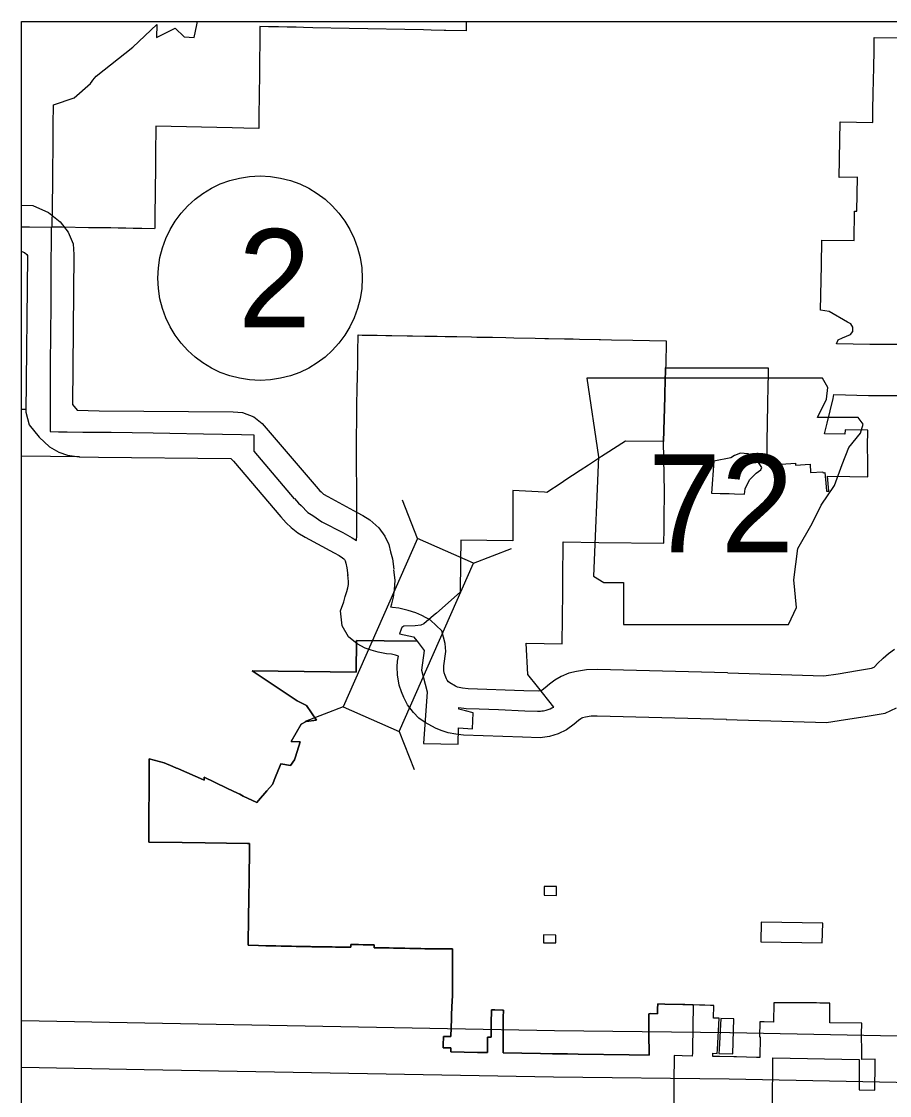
# Model space of a CAD drawing. Extents: x 670147 to 673275, y 705573 to 707613.
# Drawn here: x 670257.2 to 670341.3, y 707417.7 to 707521.7 of the extents above; entities that cross this region are included whole.
import ezdxf

# ---------------------------------------------------------------- set-up
doc = ezdxf.new("R2010")
doc.units = 0
for name, color, linetype in [('10', 7, 'Continuous'), ('20', 7, 'Continuous'), ('21', 7, 'Continuous'), ('27', 7, 'Continuous'), ('6', 7, 'Continuous'), ('R_NoPlot', 7, 'Continuous')]:
    doc.layers.add(name, color=color, linetype=linetype)

msp = doc.modelspace()

# ---------------------------------------------------------------- linework, layer by layer
at = {"layer": '10'}
msp.add_line((670260.81, 707480.01), (670261.67, 707479.72), dxfattribs=at)
for points in [[(670257.19, 707503.95), (670258.28, 707503.9), (670259.81, 707503.23), (670260.94, 707502.34), (670261.72, 707501.32), (670262.19, 707500.18), (670262.27, 707499.17), (670262.13, 707484.64), (670262.58, 707484.08)], [(670257.19, 707499.44), (670257.24, 707499.44), (670257.48, 707499.34), (670257.71, 707499.16), (670257.77, 707499.08), (670257.77, 707499), (670257.62, 707483.9), (670257.94, 707482.66), (670258.91, 707481.46), (670259.9, 707480.55), (670260.81, 707480.01)], [(670257.68, 707484.14), (670257.19, 707484.14)], [(670262.58, 707484.08), (670264.72, 707484.03), (670277.72, 707483.91), (670278.61, 707483.86), (670279.72, 707483.45), (670280.5, 707482.8), (670281.11, 707482.12), (670285.73, 707476.69), (670286.09, 707476.28), (670286.22, 707476.16), (670286.47, 707475.96), (670286.87, 707475.73), (670289.72, 707474.19), (670290.26, 707473.87), (670290.96, 707473.46), (670291.83, 707472.7), (670292.39, 707471.87), (670292.78, 707471.07), (670292.96, 707470.37), (670293.13, 707469.69), (670293.28, 707468.69)], [(670262.82, 707479.58), (670257.19, 707479.64)], [(670261.67, 707479.72), (670262.79, 707479.57), (670264.65, 707479.53), (670277.49, 707479.41), (670277.73, 707479.16), (670282.31, 707473.76), (670282.83, 707473.16), (670283.31, 707472.72), (670283.96, 707472.22), (670284.67, 707471.8), (670287.5, 707470.28), (670287.96, 707470), (670288.31, 707469.79), (670288.43, 707469.69), (670288.48, 707469.61), (670288.54, 707469.49), (670288.61, 707469.26), (670288.71, 707468.83), (670288.82, 707468.06)], [(670325.61, 707458.63), (670312.99, 707458.96), (670311.94, 707458.94), (670310.97, 707458.76), (670310.22, 707458.6), (670309.48, 707458.3), (670308.87, 707457.94), (670308.35, 707457.54), (670307.93, 707457.19), (670307.65, 707456.97), (670307.57, 707456.93), (670307.43, 707456.89), (670307.25, 707456.87), (670305.86, 707456.9), (670300.46, 707457.09), (670299.93, 707457.17), (670299.61, 707457.22), (670299.44, 707457.27), (670299.26, 707457.35), (670298.69, 707457.67), (670298.56, 707457.76), (670298.55, 707457.78), (670298.43, 707457.93), (670298.36, 707458.06), (670298.24, 707458.4), (670298.14, 707458.65), (670298.11, 707458.86), (670298.11, 707459.07), (670298.12, 707459.33), (670298.31, 707460.7), (670298.24, 707461.5), (670297.92, 707462.7), (670296.83, 707463.75), (670295.97, 707464.2), (670295.39, 707464.46), (670294.67, 707464.69), (670293.75, 707464.92), (670293.13, 707464.97), (670292.97, 707465), (670293.07, 707465.33), (670293.23, 707465.99), (670293.35, 707466.7), (670293.39, 707467.63), (670293.28, 707468.62)], [(670325.49, 707454.13), (670312.98, 707454.46), (670312.39, 707454.45), (670311.83, 707454.34), (670311.56, 707454.29), (670311.49, 707454.26), (670311.39, 707454.2), (670311.16, 707454.02), (670310.75, 707453.68), (670310.01, 707453.11), (670309.2, 707452.73), (670308.36, 707452.47), (670307.45, 707452.36), (670305.73, 707452.41), (670300.03, 707452.6), (670299.27, 707452.72), (670298.54, 707452.82), (670297.86, 707453.06), (670297.3, 707453.28), (670296.31, 707453.85), (670295.69, 707454.27), (670295.16, 707454.79), (670294.59, 707455.54), (670294.23, 707456.27), (670294.02, 707456.81), (670293.78, 707457.46), (670293.61, 707458.45), (670293.6, 707459.22), (670293.64, 707459.78), (670293.71, 707460.27), (670293.42, 707460.37), (670293.03, 707460.46), (670292.56, 707460.5), (670291.74, 707460.65), (670291.08, 707460.84), (670290.49, 707461.04), (670289.73, 707461.44), (670288.88, 707462.14), (670288.25, 707463.19), (670288.1, 707464.65), (670288.41, 707465.53), (670288.57, 707466.03), (670288.73, 707466.52), (670288.81, 707466.88), (670288.87, 707467.19), (670288.88, 707467.49), (670288.81, 707468.13)], [(670325.62, 707458.63), (670334.94, 707458.35), (670336.33, 707458.55), (670338.18, 707458.86), (670339.55, 707459.09), (670339.8, 707459.2), (670339.87, 707459.26), (670340.14, 707459.54), (670340.68, 707460.08), (670341.21, 707460.53), (670341.76, 707460.93)], [(670325.48, 707454.13), (670335.19, 707453.84), (670337.03, 707454.11), (670338.92, 707454.42), (670340.87, 707454.75), (670341.97, 707455.25)], [(670325.82, 707423.78), (670308.82, 707423.98), (670269.15, 707424.71), (670257.19, 707424.94)], [(670402.71, 707422.39), (670387.99, 707422.45), (670348.51, 707423.34), (670325.84, 707423.78)], [(670325.77, 707419.28), (670308.75, 707419.48), (670269.07, 707420.21), (670257.19, 707420.43)], [(670406.07, 707417.87), (670387.93, 707417.95), (670348.42, 707418.84), (670325.75, 707419.28)]]:
    msp.add_lwpolyline(points, dxfattribs=at)
at = {"layer": '20'}
for p, q in [((670295.55, 707471.67), (670294.11, 707475.36)), ((670300.98, 707469.27), (670304.67, 707470.7)), ((670288.36, 707455.36), (670284.67, 707453.93)), ((670293.79, 707452.96), (670295.23, 707449.27))]:
    msp.add_line(p, q, dxfattribs=at)
msp.add_lwpolyline([(670293.79, 707452.96), (670300.98, 707469.27), (670295.55, 707471.67), (670288.36, 707455.36)], close=True, dxfattribs=at)
at = {"layer": '21'}
msp.add_lwpolyline([(670311.97, 707487.18), (670313.11, 707479.57), (670312.6, 707468.02), (670313.62, 707467.39), (670315.52, 707467.39), (670315.52, 707463.33), (670331.51, 707463.33), (670332.27, 707464.98), (670332.02, 707467.64), (670332.4, 707470.69), (670333.79, 707473.1), (670334.68, 707474.87), (670335.95, 707476.78), (670336.71, 707478.81), (670337.35, 707480.46), (670338.49, 707481.85), (670338.74, 707482.74), (670338.24, 707483.38), (670334.3, 707483.38), (670335.19, 707485.15), (670335.32, 707486.29), (670334.79, 707487.17)], close=True, dxfattribs=at)
at = {"layer": '27'}
msp.add_circle((670280.31, 707496.87), 9.9, dxfattribs=at)
at = {"layer": '6'}
for points in [[(670300.29, 707521.73), (670300.27, 707520.82), (670298.3, 707520.86), (670298.16, 707520.86), (670296.89, 707520.89), (670296.14, 707520.91), (670288.95, 707521.06), (670285.42, 707521.13), (670284.51, 707521.15), (670283.8, 707521.17), (670282.94, 707521.18), (670282.09, 707521.2), (670281.14, 707521.22), (670280.3, 707521.24), (670280.29, 707520.79), (670280.29, 707520.49), (670280.28, 707519.38), (670280.26, 707518.27), (670280.26, 707517.77), (670280.25, 707517.15), (670280.24, 707516.04), (670280.23, 707515.21), (670280.23, 707514.77), (670280.22, 707514.48), (670280.2, 707512.71), (670280.2, 707512.57), (670280.19, 707511.38), (670278.74, 707511.41), (670277.62, 707511.44), (670270.21, 707511.6), (670270.19, 707508.89), (670270.18, 707507.74), (670270.17, 707507.04), (670270.17, 707506.62), (670270.16, 707506.34), (670270.15, 707505.64), (670270.14, 707504.55), (670270.12, 707503.55), (670270.11, 707502.69), (670270.1, 707501.7), (670270.09, 707501.66), (670268.87, 707501.68), (670268.01, 707501.69), (670267.29, 707501.71), (670266.57, 707501.72), (670265.86, 707501.73), (670265.13, 707501.74), (670264.41, 707501.75), (670263.69, 707501.76), (670261.14, 707501.8), (670260.18, 707501.81), (670260.18, 707502.14), (670260.2, 707503.5), (670260.21, 707504.49), (670260.22, 707505.55), (670260.23, 707506.26), (670260.23, 707506.97), (670260.24, 707507.75), (670260.25, 707509.18), (670260.26, 707509.48), (670260.28, 707511.73), (670260.3, 707513.67), (670262.3, 707514.34), (670263.87, 707515.71), (670264.05, 707515.96), (670264.12, 707516.04), (670264.42, 707516.43), (670267.98, 707519.24), (670270.31, 707521.45), (670270.29, 707520.19), (670272.09, 707521.07), (670272.96, 707520.25), (670273.93, 707520.17), (670274.18, 707521.4), (670274.24, 707521.73)], [(670344.39, 707490.45), (670339.39, 707490.45), (670336.17, 707490.52), (670336.32, 707490.9), (670336.74, 707491.08), (670337.52, 707491.4), (670337.73, 707491.7), (670337.74, 707492.13), (670337.53, 707492.45), (670337.23, 707492.62), (670335.43, 707493.64), (670334.61, 707493.78), (670334.69, 707498.13), (670334.74, 707500.54), (670337.88, 707500.51), (670337.91, 707503.37), (670338.14, 707503.36), (670338.19, 707506.64), (670336.42, 707506.62), (670336.52, 707512.02), (670339.67, 707511.96), (670339.69, 707513.14), (670339.72, 707514.78), (670339.74, 707516.01), (670339.77, 707517.32), (670339.79, 707518.9), (670339.82, 707520.19), (670342.02, 707520.16)], [(670257.19, 707501.85), (670257.97, 707501.84), (670260.07, 707501.8), (670260.06, 707499.8), (670260.05, 707499.03), (670260.03, 707493.82), (670260.02, 707491.89), (670260.01, 707491.66), (670259.99, 707488.31), (670259.97, 707484.7), (670259.96, 707482.01), (670260.77, 707482), (670261.63, 707481.99), (670263.15, 707481.97), (670265.7, 707481.94), (670265.89, 707481.94), (670269.94, 707481.89), (670271.57, 707481.86), (670274.84, 707481.8), (670278.51, 707481.73), (670279.72, 707481.71), (670279.71, 707481.05), (670279.71, 707480.1), (670283.61, 707475.51), (670283.64, 707475.53), (670284.02, 707475.09), (670284.29, 707474.85), (670284.95, 707474.18), (670285.43, 707473.87), (670286.28, 707473.28), (670288.33, 707472.24), (670289.24, 707471.72), (670289.65, 707471.47), (670289.7, 707471.94), (670289.68, 707474.66), (670289.67, 707476.31), (670289.67, 707476.69), (670289.66, 707478.51), (670289.65, 707479.69), (670289.64, 707480.79), (670289.64, 707481.07), (670289.64, 707481.53), (670289.67, 707483.07), (670289.69, 707484.55), (670289.73, 707486.2), (670289.73, 707486.57), (670289.74, 707486.93), (670289.78, 707488.93), (670289.79, 707489.71), (670289.83, 707491.37), (670290.21, 707491.36), (670291.65, 707491.34), (670292.49, 707491.32), (670293.08, 707491.31), (670294.55, 707491.29), (670295.07, 707491.28), (670296.26, 707491.26), (670296.58, 707491.25), (670296.69, 707491.25), (670297.05, 707491.25), (670297.48, 707491.24), (670298.24, 707491.23), (670299.36, 707491.21), (670300.8, 707491.18), (670301.32, 707491.17), (670301.95, 707491.16), (670302.82, 707491.14), (670304.11, 707491.12), (670304.91, 707491.1), (670306.96, 707491.06), (670307.89, 707491.04), (670308.26, 707491.04), (670309.81, 707491.01), (670310.15, 707491), (670310.63, 707490.99), (670311.25, 707490.97), (670313.16, 707490.93), (670313.3, 707490.93), (670314.37, 707490.91), (670316.42, 707490.86), (670319.67, 707490.79), (670319.61, 707488.42), (670319.6, 707488.19)], [(670319.6, 707488.19), (670319.56, 707486.71), (670319.54, 707485.93), (670319.52, 707485.37), (670319.4, 707481.05), (670315.7, 707481.09), (670313.76, 707479.83), (670313.4, 707479.59), (670312.13, 707478.76), (670311.32, 707478.23), (670309.85, 707477.27), (670309.72, 707477.18), (670309.48, 707477.03), (670308.09, 707476.12), (670307.87, 707476.13), (670304.8, 707476.31), (670304.8, 707475.44), (670304.81, 707471.42), (670299.75, 707471.51), (670299.74, 707469.41), (670299.71, 707466.46), (670297.39, 707464.44), (670297.11, 707464.19), (670296.18, 707463.38), (670295.89, 707463.27), (670295.35, 707463.19), (670294.25, 707463.15), (670294.04, 707463.04), (670293.98, 707462.87), (670293.81, 707462.42), (670293.81, 707462.42), (670295.18, 707462.12), (670295.53, 707461.71), (670292.34, 707461.75), (670289.66, 707461.79), (670289.61, 707458.72), (670279.56, 707458.85), (670283.91, 707455.95), (670284.8, 707455.48), (670285.78, 707454.06), (670284.79, 707453.92), (670284.3, 707453.68), (670283.31, 707451.98), (670284.2, 707451.97), (670283.74, 707450.52), (670283.64, 707450.21), (670283.27, 707449.68), (670282.33, 707449.83), (670282.26, 707449.67), (670281.8, 707448.57), (670281.5, 707447.84), (670280.96, 707447.23), (670280.15, 707446.27), (670280.01, 707446.1), (670278.68, 707446.71), (670278.34, 707446.88), (670278.13, 707446.98), (670277.15, 707447.45), (670275.9, 707448.06), (670274.88, 707448.55), (670274.89, 707448.26), (670274.54, 707448.42), (670272.69, 707449.22), (670272.33, 707449.38), (670272.23, 707449.42), (670271.86, 707449.58), (670271.01, 707449.93), (670269.57, 707450.33), (670269.56, 707447.38), (670269.54, 707444.92), (670269.53, 707442.25), (670272.76, 707442.21), (670275, 707442.18), (670277.07, 707442.15), (670279.09, 707442.12), (670279.3, 707442.12), (670279.29, 707441.31), (670279.28, 707440.84), (670279.28, 707440.36), (670279.27, 707439.89), (670279.26, 707439.42), (670279.25, 707438.95), (670279.25, 707438.47), (670279.24, 707438), (670279.23, 707437.53), (670279.23, 707437.2), (670279.23, 707437.06), (670279.22, 707436.7), (670279.22, 707436.58), (670279.21, 707436.11), (670279.2, 707435.64), (670279.2, 707435.16), (670279.19, 707434.69), (670279.18, 707434.22), (670279.18, 707433.77), (670279.17, 707433.55), (670279.16, 707432.95), (670279.16, 707432.26), (670280.17, 707432.23), (670280.86, 707432.21)], [(670319.47, 707474.31), (670319.48, 707475.46), (670319.49, 707476.18), (670319.4, 707481.05), (670319.52, 707485.37), (670319.54, 707485.93), (670319.56, 707486.71), (670319.6, 707488.19), (670321.84, 707488.19), (670323.38, 707488.2), (670329.52, 707488.2), (670329.49, 707485.78), (670329.48, 707485.38), (670329.47, 707484.49), (670329.45, 707482.98), (670329.42, 707480.9), (670329.41, 707479.85), (670329.41, 707479.69), (670329.4, 707478.75), (670332.18, 707478.94), (670332.19, 707478.75), (670333.6, 707478.84), (670333.65, 707478.04), (670334.84, 707478.12), (670334.85, 707478.03), (670335.03, 707478.04), (670335.15, 707476.66), (670335.19, 707476.23), (670335.41, 707476.23), (670335.28, 707477.7), (670337.45, 707477.66), (670339.2, 707477.63), (670339.18, 707479.13), (670339.16, 707480.57), (670339.19, 707482.15), (670336.99, 707482.18), (670336.95, 707481.75), (670334.99, 707481.8), (670335.24, 707482.82), (670335.83, 707485.21), (670335.91, 707485.61), (670339.27, 707485.52), (670341.99, 707485.5)], [(670279.21, 707436.11), (670279.22, 707436.58), (670279.22, 707436.7), (670279.23, 707437.06), (670279.23, 707437.2), (670279.23, 707437.53), (670279.24, 707438), (670279.25, 707438.47), (670279.25, 707438.95), (670279.26, 707439.42), (670279.27, 707439.89), (670279.28, 707440.36), (670279.28, 707440.84), (670279.29, 707441.31), (670279.3, 707442.12), (670279.09, 707442.12), (670277.07, 707442.15), (670275, 707442.18), (670272.76, 707442.21), (670269.53, 707442.25), (670269.54, 707444.92), (670269.56, 707447.38), (670269.57, 707450.33), (670271.01, 707449.93), (670271.86, 707449.58), (670272.23, 707449.42), (670272.33, 707449.38), (670272.69, 707449.22), (670274.54, 707448.42), (670274.89, 707448.26), (670274.88, 707448.55), (670275.9, 707448.06), (670277.15, 707447.45), (670278.13, 707446.98), (670278.34, 707446.88), (670278.68, 707446.71), (670280.01, 707446.1), (670280.15, 707446.27), (670280.96, 707447.23), (670281.5, 707447.84), (670281.8, 707448.57), (670282.26, 707449.67), (670282.33, 707449.83), (670283.27, 707449.68), (670283.64, 707450.21), (670283.74, 707450.52), (670284.2, 707451.97), (670283.31, 707451.98), (670284.3, 707453.68), (670284.79, 707453.92), (670285.78, 707454.06), (670284.8, 707455.48), (670283.91, 707455.95), (670279.56, 707458.85), (670289.61, 707458.72), (670289.66, 707461.79), (670292.34, 707461.75), (670295.53, 707461.71), (670296.22, 707460.81), (670295.94, 707458.89), (670296.49, 707456.81), (670296.16, 707451.79), (670299.49, 707451.74), (670299.52, 707453.31), (670300.88, 707453.23), (670300.94, 707454.76), (670300.2, 707454.97), (670299.56, 707455.14), (670299.56, 707455.3), (670300.29, 707455.2), (670301.53, 707455.15), (670303.42, 707455.08), (670305.97, 707454.98), (670307.18, 707454.94), (670307.27, 707454.94), (670307.38, 707454.94), (670307.49, 707454.94), (670307.62, 707454.95), (670307.77, 707454.97), (670307.91, 707455), (670308.02, 707455.03), (670308.22, 707455.09), (670308.4, 707455.16), (670308.59, 707455.24), (670308.76, 707455.33), (670308.76, 707455.33), (670307.18, 707457.33), (670306.26, 707458.5), (670306.08, 707461.53), (670309.59, 707461.47), (670309.64, 707466.48), (670309.65, 707467.71), (670309.68, 707471.33), (670313.12, 707471.28), (670319.43, 707471.19), (670319.44, 707471.5), (670319.45, 707472.28), (670319.45, 707472.96), (670319.46, 707473.63), (670319.47, 707474.31)], [(670298.8, 707421.94), (670298.8, 707422.32), (670298.8, 707422.33), (670298.3, 707422.33), (670298.04, 707422.34), (670298.04, 707422.6), (670298.07, 707423.43), (670298.79, 707423.43), (670298.86, 707425.13), (670298.87, 707425.76), (670298.89, 707426.05), (670298.9, 707426.31), (670298.92, 707426.86), (670298.94, 707427.41), (670298.94, 707427.94), (670298.94, 707428.16), (670298.94, 707428.47), (670298.94, 707428.91), (670298.94, 707429.03), (670298.94, 707429.54), (670298.94, 707429.66), (670298.94, 707430.1), (670298.94, 707430.41), (670298.94, 707430.64), (670298.94, 707431.16), (670298.94, 707431.41), (670298.94, 707431.91), (670298.71, 707431.91), (670298.22, 707431.92), (670298.11, 707431.92), (670297.74, 707431.92), (670297.49, 707431.92), (670297.24, 707431.92), (670296.96, 707431.93), (670296.76, 707431.93), (670296.43, 707431.93), (670296.28, 707431.93), (670295.9, 707431.94), (670295.79, 707431.94), (670295.37, 707431.95), (670295.31, 707431.95), (670294.84, 707431.96), (670294.82, 707431.96), (670294.33, 707431.97), (670294.31, 707431.97), (670293.84, 707431.98), (670293.78, 707431.98), (670293.34, 707431.99), (670293.24, 707431.99), (670292.82, 707432), (670292.72, 707432), (670292.3, 707432.01), (670292.18, 707432.01), (670291.81, 707432.02), (670291.65, 707432.02), (670291.35, 707432.02), (670291.35, 707432.3), (670291.13, 707432.3), (670290.8, 707432.31), (670290.59, 707432.31), (670290.3, 707432.31), (670289.86, 707432.32), (670289.64, 707432.32), (670289.1, 707432.33), (670289.1, 707432.07), (670288.61, 707432.07), (670287.97, 707432.07), (670287.77, 707432.08), (670287.61, 707432.09), (670287.28, 707432.1), (670287.01, 707432.1), (670286.78, 707432.11), (670286.44, 707432.11), (670286.29, 707432.11), (670285.81, 707432.11), (670285.31, 707432.12), (670285.21, 707432.13), (670284.81, 707432.13), (670284.61, 707432.13), (670284.32, 707432.14), (670284.01, 707432.15), (670283.82, 707432.15), (670283.36, 707432.16), (670283.32, 707432.16), (670283.1, 707432.16), (670282.84, 707432.16), (670282.36, 707432.18), (670281.85, 707432.19), (670281.36, 707432.2), (670280.86, 707432.21), (670280.17, 707432.23), (670279.16, 707432.26), (670279.16, 707432.95), (670279.17, 707433.55), (670279.18, 707433.77), (670279.18, 707434.22), (670279.19, 707434.69), (670279.2, 707435.16), (670279.2, 707435.64), (670279.21, 707436.11)], [(670280.86, 707432.21), (670281.36, 707432.2), (670281.85, 707432.19), (670282.36, 707432.18), (670282.84, 707432.16), (670283.1, 707432.16), (670283.32, 707432.16), (670283.36, 707432.16), (670283.82, 707432.15), (670284.01, 707432.15), (670284.32, 707432.14), (670284.61, 707432.13), (670284.81, 707432.13), (670285.21, 707432.13), (670285.31, 707432.12), (670285.81, 707432.11), (670286.29, 707432.11), (670286.44, 707432.11), (670286.78, 707432.11), (670287.01, 707432.1), (670287.28, 707432.1), (670287.61, 707432.09), (670287.77, 707432.08), (670287.97, 707432.07), (670288.61, 707432.07), (670289.1, 707432.07), (670289.1, 707432.33), (670289.64, 707432.32), (670289.86, 707432.32), (670290.3, 707432.31), (670290.59, 707432.31), (670290.8, 707432.31), (670291.13, 707432.3), (670291.35, 707432.3), (670291.35, 707432.02), (670291.65, 707432.02), (670291.81, 707432.02), (670292.18, 707432.01), (670292.3, 707432.01), (670292.72, 707432), (670292.82, 707432), (670293.24, 707431.99), (670293.34, 707431.99), (670293.78, 707431.98), (670293.84, 707431.98), (670294.31, 707431.97), (670294.33, 707431.97), (670294.82, 707431.96), (670294.84, 707431.96), (670295.31, 707431.95), (670295.37, 707431.95), (670295.79, 707431.94), (670295.9, 707431.94), (670296.28, 707431.93), (670296.43, 707431.93), (670296.76, 707431.93), (670296.96, 707431.93), (670297.24, 707431.92), (670297.49, 707431.92), (670297.74, 707431.92), (670298.11, 707431.92), (670298.22, 707431.92), (670298.71, 707431.91), (670298.94, 707431.91), (670298.94, 707431.41), (670298.94, 707431.16), (670298.94, 707430.64), (670298.94, 707430.41), (670298.94, 707430.1), (670298.94, 707429.66), (670298.94, 707429.54), (670298.94, 707429.03), (670298.94, 707428.91), (670298.94, 707428.47), (670298.94, 707428.16), (670298.94, 707427.94), (670298.94, 707427.41), (670298.92, 707426.86), (670298.9, 707426.31), (670298.89, 707426.05), (670298.87, 707425.76), (670298.86, 707425.13), (670298.79, 707423.43), (670298.07, 707423.43), (670298.04, 707422.6), (670298.04, 707422.34), (670298.3, 707422.33), (670298.8, 707422.33), (670298.8, 707422.32), (670298.8, 707421.94), (670301.39, 707421.89), (670302.33, 707421.88), (670302.33, 707423.36), (670302.7, 707423.35), (670302.7, 707423.94), (670302.71, 707424.69), (670302.72, 707426), (670303.05, 707426), (670303.05, 707426), (670303.8, 707425.99)], [(670329.97, 707416.63), (670329.98, 707421.37), (670338.34, 707421.2), (670338.36, 707418.27), (670339.86, 707418.24), (670339.9, 707420.79), (670339.91, 707421.24), (670338.6, 707421.2), (670338.6, 707421.56), (670338.6, 707421.61), (670338.61, 707421.91), (670338.59, 707423.65), (670338.62, 707424.71), (670335.52, 707424.75), (670335.51, 707426.66), (670335.09, 707426.66), (670334.54, 707426.66), (670334.22, 707426.67), (670333.99, 707426.67), (670333.44, 707426.67), (670332.77, 707426.68), (670332.45, 707426.68), (670331.28, 707426.69), (670330.08, 707426.69), (670330.06, 707424.82), (670329.14, 707424.83), (670328.79, 707424.83), (670328.72, 707424.83), (670328.69, 707423.38), (670328.76, 707423.38), (670328.73, 707421.39), (670328.41, 707421.4), (670326.46, 707421.44), (670326.38, 707421.44), (670326.2, 707421.45), (670324.83, 707421.48), (670324.65, 707421.48), (670324.42, 707421.48), (670324.18, 707421.49), (670324.19, 707421.8), (670324.61, 707421.78), (670324.63, 707422.16), (670324.8, 707425.19), (670324.24, 707425.21), (670324.27, 707426.43), (670324.23, 707426.43), (670323.95, 707426.44), (670323.41, 707426.45), (670323.25, 707426.46), (670322.87, 707426.47), (670322.27, 707426.49), (670322.22, 707426.49), (670321.47, 707426.51), (670321.28, 707426.52), (670319.51, 707426.57), (670318.85, 707426.59), (670318.83, 707426.1), (670318.82, 707425.63), (670318.1, 707425.64), (670317.97, 707425.62), (670317.97, 707425.02), (670317.97, 707424.94), (670317.98, 707423.78), (670318, 707421.61), (670316.08, 707421.64), (670311.14, 707421.72), (670310.09, 707421.74), (670308.9, 707421.76), (670308.63, 707421.76), (670307.49, 707421.78), (670303.85, 707421.85), (670303.86, 707423.34), (670303.87, 707423.84), (670303.87, 707423.84), (670303.87, 707424.64), (670303.87, 707424.66), (670303.87, 707425.27), (670303.88, 707425.98), (670303.8, 707425.99), (670303.05, 707426), (670303.05, 707426), (670302.72, 707426), (670302.71, 707424.69), (670302.7, 707423.94), (670302.7, 707423.35), (670302.33, 707423.36), (670302.33, 707421.88), (670301.39, 707421.89), (670298.8, 707421.94)], [(670303.8, 707425.99), (670303.88, 707425.98), (670303.87, 707425.27), (670303.87, 707424.66), (670303.87, 707424.64), (670303.87, 707423.84), (670303.87, 707423.84), (670303.86, 707423.34), (670303.85, 707421.85), (670307.49, 707421.78), (670308.63, 707421.76), (670308.9, 707421.76), (670310.09, 707421.74), (670311.14, 707421.72), (670316.08, 707421.64), (670318, 707421.61), (670317.98, 707423.78), (670317.97, 707424.94), (670317.97, 707425.02), (670317.97, 707425.62), (670318.1, 707425.64), (670318.82, 707425.63), (670318.83, 707426.1), (670318.85, 707426.59), (670319.51, 707426.57), (670321.28, 707426.52), (670321.47, 707426.51), (670322.22, 707426.49), (670322.27, 707426.49), (670322.19, 707422.21), (670322.19, 707421.84), (670322.18, 707421.53), (670321.19, 707421.55), (670320.42, 707421.57), (670320.41, 707418.98), (670320.41, 707416.84)]]:
    msp.add_lwpolyline(points, dxfattribs=at)
for points in [[(670327.23, 707475.96), (670327.3, 707476.48), (670327.59, 707477.08), (670327.75, 707477.38), (670328, 707477.61), (670328.37, 707477.99), (670328.81, 707478.31), (670328.93, 707478.53), (670328.33, 707479.4), (670327.58, 707479.84), (670326.84, 707479.91), (670326.29, 707479.71), (670325.92, 707479.47), (670324.26, 707479.15), (670324.03, 707476.05), (670324.9, 707476.03), (670325.77, 707476), (670326.27, 707475.99)], [(670309.02, 707437.07), (670309.03, 707437.49), (670309.03, 707437.94), (670307.85, 707437.96), (670307.85, 707437.79), (670307.84, 707437.51), (670307.84, 707437.1)], [(670334.78, 707432.51), (670334.83, 707434.39), (670328.85, 707434.49), (670328.82, 707432.6)], [(670308.96, 707432.48), (670308.97, 707433.02), (670308.97, 707433.24), (670307.78, 707433.27), (670307.77, 707432.56), (670307.77, 707432.51)], [(670326.12, 707421.75), (670326.22, 707425.13), (670324.95, 707425.18), (670324.78, 707422.16), (670324.76, 707421.78)]]:
    msp.add_lwpolyline(points, close=True, dxfattribs=at)
at = {"layer": 'R_NoPlot'}
msp.add_lwpolyline([(670257.19, 707521.73), (670842.89, 707521.73), (670842.89, 706992.57), (670257.19, 706992.57)], close=True, dxfattribs=at)

# ---------------------------------------------------------------- texts
at = {"layer": '21'}
msp.add_text('72', height=9.504, dxfattribs=at).set_placement((670317.88, 707470.31))
at = {"layer": '27'}
msp.add_text('2', height=9.5, dxfattribs=at).set_placement((670278.18, 707492.12))

doc.saveas('drawing.dxf')
